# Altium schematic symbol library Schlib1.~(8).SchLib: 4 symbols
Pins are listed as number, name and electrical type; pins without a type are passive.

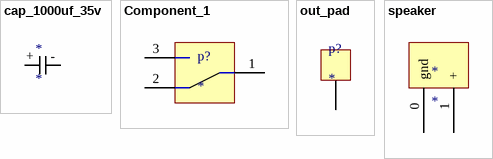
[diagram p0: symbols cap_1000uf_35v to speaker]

## cap_1000uf_35v
designator *
pins: + 2, - 3

## Component_1
designator p?
pins: 1 in, 2, 3

## out_pad
designator p?
footprint pad
pins: 0

## speaker
designator *
footprint speaker
pins: 0 gnd, 1 +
